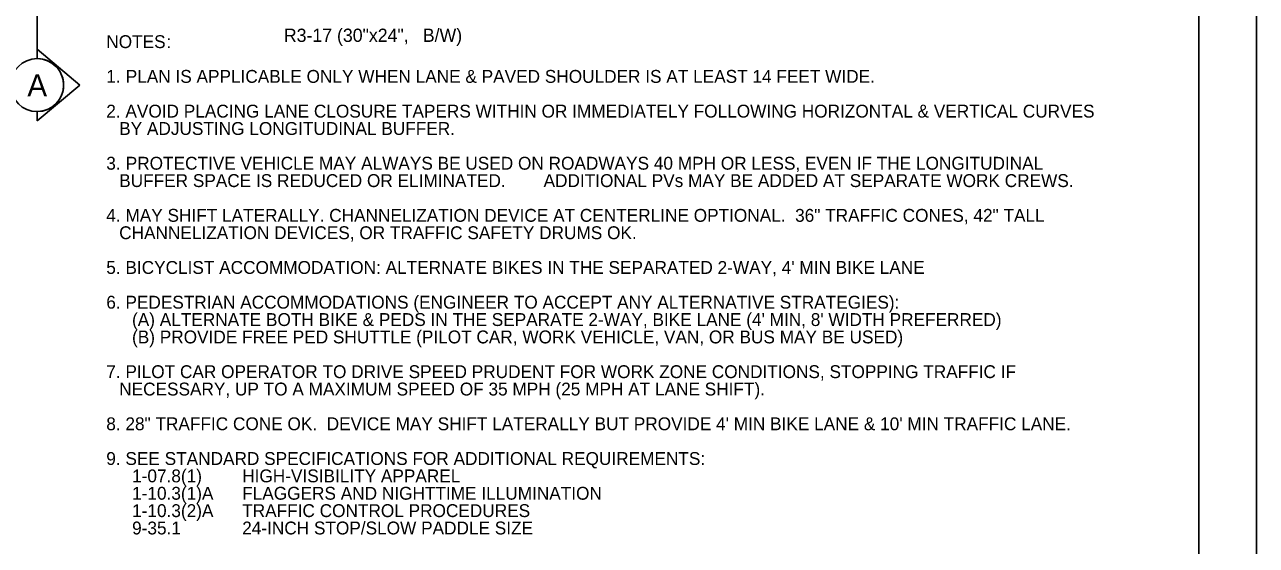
# Model space of a CAD drawing. Extents: x 99998.9 to 100095.7, y 99995 to 100010.7.
# Drawn here: x 100049.37 to 100056.06, y 100002.8 to 100005.63 of the extents above; entities that cross this region are included whole.
import ezdxf

# ---------------------------------------------------------------- set-up
doc = ezdxf.new("R2010")
doc.units = 0
for name, color, linetype in [('SH_GI_GeneralNotesBodyText', 7, 'Continuous'), ('SH_GI_PlotLimits', 7, 'Continuous'), ('SH_GI_SectionCut', 7, 'Continuous'), ('SH_GI_SheetBorder', 7, 'Continuous'), ('TR_WZ_WorkZoneDetails', 7, 'Continuous')]:
    doc.layers.add(name, color=color, linetype=linetype)

msp = doc.modelspace()

# ---------------------------------------------------------------- linework, layer by layer
at = {"layer": 'SH_GI_PlotLimits'}
msp.add_lwpolyline([(100039.0625, 99999.6875), (100056.0625, 99999.6875), (100056.0625, 100010.6875), (100039.0625, 100010.6875)], close=True, dxfattribs=at)
at = {"layer": 'SH_GI_SectionCut'}
for p, q in [((100049.4338, 100007.7396), (100049.4338, 100005.4996)), ((100049.4337, 100005.4996), (100049.4337, 100005.4487)), ((100049.6664, 100005.3048), (100049.4337, 100005.4996)), ((100049.4337, 100005.1099), (100049.6664, 100005.3048)), ((100049.4337, 100005.1608), (100049.4337, 100005.1099))]:
    msp.add_line(p, q, dxfattribs=at)
msp.add_circle((100049.4338, 100005.3048), 0.144, dxfattribs=at)
msp.add_arc((100049.4338, 100005.3048), 0.144, 269.99779, 90.00221, dxfattribs=at)
at = {"layer": 'SH_GI_SheetBorder'}
msp.add_line((100055.75, 100010.375), (100055.75, 100000), dxfattribs=at)

# ---------------------------------------------------------------- texts
at = {"layer": 'SH_GI_GeneralNotesBodyText'}
for s, p in [('NOTES', (100049.8098, 100005.5061)), (':', (100050.1373, 100005.5061)), ('1. ', (100049.8098, 100005.3171)), ('PLAN IS APPLICABLE ONLY WHEN LANE & PAVED SHOULDER IS AT LEAST 14 FEET WIDE.', (100049.9155, 100005.3171)), ('2. AVOID PLACING LANE CLOSURE TAPERS WITHIN OR IMMEDIATELY FOLLOWING HORIZONTAL & VERTICAL CURVES ', (100049.8098, 100005.1281)), ('BY ADJUSTING LONGITUDINAL BUFFER.', (100049.88, 100005.0336)), ('3. ', (100049.8098, 100004.8446)), ('PROTECTIVE VEHICLE MAY ALWAYS BE USED ON ROADWAYS 40 MPH OR LESS, EVEN IF THE LONGITUDINAL ', (100049.9155, 100004.8446)), ('BUFFER SPACE IS REDUCED OR ELIMINATED.', (100049.88, 100004.7501)), ('  ADDITIONAL PVs MAY BE ADDED AT SEPARATE WORK CREWS.', (100052.1353, 100004.7501)), ('4. MAY SHIFT LATERALLY. CHANNELIZATION DEVICE AT CENTERLINE OPTIONAL.  36" TRAFFIC CONES, 42" TALL ', (100049.8098, 100004.5611)), ('CHANNELIZATION DEVICES, OR TRAFFIC SAFETY DRUMS OK.', (100049.88, 100004.4666)), ("5. BICYCLIST ACCOMMODATION: ALTERNATE BIKES IN THE SEPARATED 2-WAY, 4' MIN BIKE LANE", (100049.8098, 100004.2776)), ('6. PEDESTRIAN ACCOMMODATIONS (ENGINEER TO ACCEPT ANY ALTERNATIVE STRATEGIES):', (100049.8098, 100004.0886)), ("(A) ALTERNATE BOTH BIKE & PEDS IN THE SEPARATE 2-WAY, BIKE LANE (4' MIN, 8' WIDTH PREFERRED)", (100049.9498, 100003.9941)), ('(B) PROVIDE FREE PED SHUTTLE (PILOT CAR, WORK VEHICLE, VAN, OR BUS MAY BE USED)', (100049.9498, 100003.8996)), ('7. PILOT CAR OPERATOR TO DRIVE SPEED PRUDENT FOR WORK ZONE CONDITIONS, STOPPING TRAFFIC IF ', (100049.8098, 100003.7106)), ('NECESSARY, UP TO A MAXIMUM SPEED OF 35 MPH (25 MPH AT LANE SHIFT).', (100049.88, 100003.6161)), ('8. 28" TRAFFIC CONE OK.  DEVICE MAY SHIFT LATERALLY BUT PROVIDE 4\' MIN BIKE LANE & 10\' MIN TRAFFIC LANE.', (100049.8098, 100003.4271)), ('9. SEE STANDARD SPECIFICATIONS FOR ADDITIONAL REQUIREMENTS:', (100049.8098, 100003.2381)), ('1-07.8(1) ', (100049.9502, 100003.1436)), ('HIGH-VISIBILITY APPAREL', (100050.5487, 100003.1436)), ('1-10.3(1)A ', (100049.9502, 100003.0491)), ('FLAGGERS AND NIGHTTIME ILLUMINATION', (100050.5487, 100003.0491)), ('1-10.3(2)A', (100049.9502, 100002.9546)), ('TRAFFIC CONTROL PROCEDURES', (100050.5487, 100002.9546)), ('9-35.1', (100049.9502, 100002.8601)), ('24-INCH STOP/SLOW PADDLE SIZE', (100050.5487, 100002.8601))]:
    msp.add_text(s, height=0.07, rotation=360, dxfattribs=at).set_placement(p)
at = {"layer": 'SH_GI_SectionCut'}
msp.add_text('A', height=0.12, rotation=0.00995, dxfattribs=at).set_placement((100049.3809, 100005.2439))
at = {"layer": 'TR_WZ_WorkZoneDetails'}
for s, p in [('R3-17 (30"x24",', (100050.7752, 100005.5399)), ('B/W)', (100051.5306, 100005.5399))]:
    msp.add_text(s, height=0.072, rotation=360, dxfattribs=at).set_placement(p)

doc.saveas('drawing.dxf')
